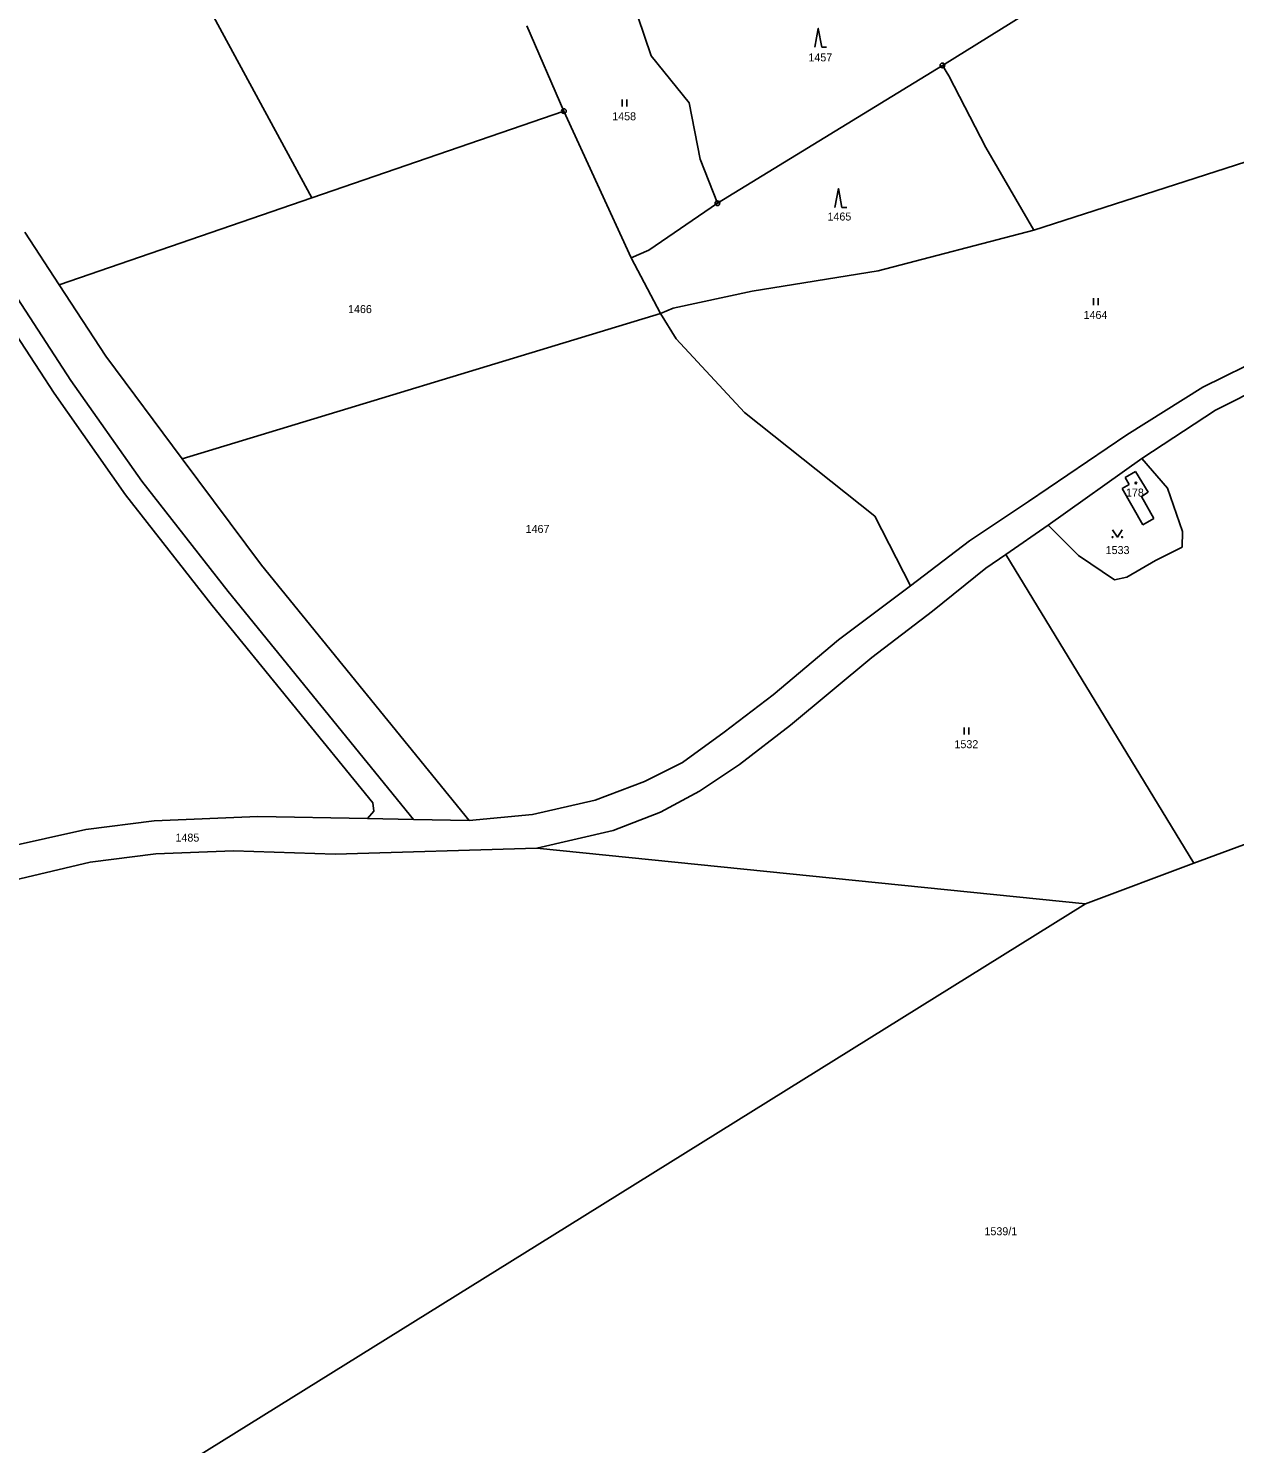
# Model space of a CAD drawing. Extents: x -601131 to -597152, y -1058536 to -1055911.
# Drawn here: x -600092 to -599835.8, y -1057934.2 to -1057633.6 of the extents above; entities that cross this region are included whole.
import ezdxf
from ezdxf.enums import TextEntityAlignment as Align

# ---------------------------------------------------------------- set-up
doc = ezdxf.new("R2010")
doc.units = 0
doc.header["$LTSCALE"] = 0.68
for name, color, linetype, lineweight in [('1', 7, 'Continuous', 25), ('3', 7, 'Continuous', 25), ('5', 7, 'Continuous', 25), ('8', 7, 'Continuous', 25)]:
    doc.layers.add(name, color=color, linetype=linetype, lineweight=lineweight)
doc.layers.add('2', color=7, linetype='Continuous')

msp = doc.modelspace()

# ---------------------------------------------------------------- linework, layer by layer
at = {"layer": '1'}
for p, q in [((-600031.79, -1057669.6), (-600081.73, -1057577.23)), ((-599959.7, -1057639.42), (-599962.58, -1057631.06)), ((-599880.67, -1057630.78), (-599897.86, -1057641.47)), ((-599978.26, -1057651.17), (-599986.09, -1057633.05)), ((-599951.67, -1057649.45), (-599959.7, -1057639.42)), ((-599897.86, -1057641.47), (-599945.66, -1057670.73)), ((-599896.49, -1057643.71), (-599897.86, -1057641.47)), ((-599888.68, -1057658.87), (-599896.49, -1057643.71)), ((-599782.01, -1057645.31), (-599878.46, -1057676.47)), ((-599949.29, -1057661.41), (-599951.67, -1057649.45)), ((-599978.26, -1057651.17), (-600031.79, -1057669.6)), ((-599963.98, -1057682.33), (-599978.26, -1057651.17)), ((-599878.46, -1057676.47), (-599888.68, -1057658.87)), ((-599945.66, -1057670.73), (-599949.29, -1057661.41)), ((-600085.43, -1057688.07), (-600031.79, -1057669.6)), ((-599945.66, -1057670.73), (-599960.2, -1057680.68)), ((-600092.74, -1057676.87), (-600085.43, -1057688.07)), ((-599911.5, -1057685.13), (-599878.46, -1057676.47)), ((-600100.49, -1057681.44), (-600082.92, -1057708.39)), ((-599960.2, -1057680.68), (-599963.98, -1057682.33)), ((-599963.98, -1057682.33), (-599957.74, -1057694.14)), ((-600104.38, -1057683.71), (-600086.5, -1057711.11)), ((-599938.24, -1057689.4), (-599911.5, -1057685.13)), ((-600075.53, -1057703.25), (-600085.43, -1057688.07)), ((-599955.07, -1057693), (-599938.24, -1057689.4)), ((-600059.3, -1057725.04), (-599957.74, -1057694.14)), ((-599957.74, -1057694.14), (-599955.07, -1057693)), ((-599954.38, -1057699.57), (-599957.74, -1057694.14)), ((-599939.91, -1057715.17), (-599954.38, -1057699.57)), ((-599820.76, -1057698.99), (-599842.59, -1057709.8)), ((-600059.3, -1057725.04), (-600075.53, -1057703.25)), ((-599839.9, -1057714.66), (-599819.15, -1057704.19)), ((-600082.92, -1057708.39), (-600067.9, -1057729.77)), ((-599842.59, -1057709.8), (-599858.7, -1057719.94)), ((-600086.5, -1057711.11), (-600071.35, -1057732.65)), ((-599912.24, -1057737.19), (-599939.91, -1057715.17)), ((-599855.56, -1057724.96), (-599839.9, -1057714.66)), ((-599858.7, -1057719.94), (-599879.62, -1057734.06)), ((-600042.5, -1057747.6), (-600059.3, -1057725.04)), ((-599875.39, -1057739.14), (-599855.56, -1057724.96)), ((-599850.1, -1057731.26), (-599855.56, -1057724.96)), ((-599859.04, -1057728.99), (-599856.91, -1057727.72)), ((-599856.91, -1057727.72), (-599854.22, -1057732.12)), ((-600067.9, -1057729.77), (-600049.57, -1057753.17)), ((-599859.68, -1057731.31), (-599858.2, -1057730.47)), ((-599858.2, -1057730.47), (-599859.04, -1057728.99)), ((-599846.88, -1057740.43), (-599850.1, -1057731.26)), ((-600071.35, -1057732.65), (-600052.94, -1057756.15)), ((-599879.62, -1057734.06), (-599892.09, -1057742.45)), ((-599855.29, -1057739.02), (-599859.68, -1057731.31)), ((-599854.22, -1057732.12), (-599855.63, -1057733.04)), ((-599855.63, -1057733.04), (-599852.97, -1057737.71)), ((-599904.67, -1057751.96), (-599912.24, -1057737.19)), ((-599884.41, -1057745.32), (-599875.39, -1057739.14)), ((-599875.39, -1057739.14), (-599868.99, -1057745.58)), ((-599852.97, -1057737.71), (-599855.29, -1057739.02)), ((-599892.09, -1057742.45), (-599904.67, -1057751.96)), ((-599846.99, -1057743.76), (-599846.88, -1057740.43)), ((-599888.63, -1057748.21), (-599884.41, -1057745.32)), ((-599844.46, -1057810.92), (-599884.41, -1057745.32)), ((-599868.99, -1057745.58), (-599861.36, -1057750.72)), ((-599852.64, -1057746.62), (-599846.99, -1057743.76)), ((-599998.39, -1057801.82), (-600042.5, -1057747.6)), ((-599899.96, -1057757.4), (-599888.63, -1057748.21)), ((-599858.73, -1057750.14), (-599852.64, -1057746.62)), ((-599904.67, -1057751.96), (-599919.94, -1057763.49)), ((-599861.36, -1057750.72), (-599858.73, -1057750.14)), ((-600049.57, -1057753.17), (-600010.2, -1057801.61)), ((-600052.94, -1057756.15), (-600018.85, -1057798.07)), ((-599912.87, -1057767.24), (-599899.96, -1057757.4)), ((-599919.94, -1057763.49), (-599933.84, -1057775.17)), ((-599930.12, -1057781.57), (-599912.87, -1057767.24)), ((-599933.84, -1057775.17), (-599944.19, -1057783.06)), ((-599940.94, -1057789.94), (-599930.12, -1057781.57)), ((-599944.19, -1057783.06), (-599953.07, -1057789.52)), ((-599953.07, -1057789.52), (-599961.12, -1057793.57)), ((-599949.45, -1057795.62), (-599940.94, -1057789.94)), ((-599961.12, -1057793.57), (-599971.59, -1057797.51)), ((-599957.76, -1057800.08), (-599949.45, -1057795.62)), ((-600018.58, -1057799.86), (-600019.99, -1057801.43)), ((-600018.85, -1057798.07), (-600018.58, -1057799.86)), ((-599971.59, -1057797.51), (-599984.92, -1057800.58)), ((-599967.79, -1057803.97), (-599957.76, -1057800.08)), ((-600065.27, -1057801.92), (-600079.8, -1057803.77)), ((-600043.22, -1057801), (-600065.27, -1057801.92)), ((-600019.99, -1057801.43), (-600043.22, -1057801)), ((-600010.2, -1057801.61), (-600019.99, -1057801.43)), ((-600010.2, -1057801.61), (-599998.39, -1057801.82)), ((-599984.92, -1057800.58), (-599998.39, -1057801.82)), ((-600079.8, -1057803.77), (-600096.87, -1057807.55)), ((-599983.99, -1057807.73), (-599967.79, -1057803.97)), ((-600078.87, -1057810.71), (-600064.88, -1057808.91)), ((-600064.88, -1057808.91), (-600048.42, -1057808.26)), ((-600048.42, -1057808.26), (-600026.8, -1057808.95)), ((-600026.8, -1057808.95), (-599983.99, -1057807.73)), ((-599867.48, -1057819.51), (-599983.99, -1057807.73)), ((-600094.97, -1057814.53), (-600078.87, -1057810.71)), ((-599844.46, -1057810.92), (-599867.48, -1057819.51)), ((-599980.76, -1057890.01), (-599867.48, -1057819.51)), ((-600094.05, -1057960.5), (-599980.76, -1057890.01))]:
    msp.add_line(p, q, dxfattribs=at)
msp.add_lwpolyline([(-599844.46, -1057810.92), (-599812.82, -1057799.18), (-599800.5, -1057863.35)], dxfattribs=at)
at = {"layer": '3'}
for p, q in [((-599923.48, -1057637.63), (-599922.484, -1057637.63)), ((-599965.871, -1057650.23), (-599965.871, -1057648.73)), ((-599964.87, -1057650.23), (-599964.87, -1057648.73)), ((-599919.2, -1057671.64), (-599918.204, -1057671.64)), ((-599865.771, -1057692.4), (-599865.771, -1057690.9)), ((-599864.77, -1057692.4), (-599864.77, -1057690.9)), ((-599893.251, -1057783.58), (-599893.251, -1057782.08)), ((-599892.25, -1057783.58), (-599892.25, -1057782.08))]:
    msp.add_line(p, q, dxfattribs=at)
for points in [[(-599923.48, -1057637.63), (-599924.23, -1057633.63), (-599924.98, -1057637.63)], [(-599919.2, -1057671.64), (-599919.95, -1057667.64), (-599920.7, -1057671.64)], [(-599861.73, -1057740.129), (-599860.73, -1057741.63), (-599859.73, -1057740.129)]]:
    msp.add_lwpolyline(points, dxfattribs=at)
for centre in [(-599861.73, -1057741.6295), (-599859.73, -1057741.6295)]:
    msp.add_circle(centre, 0.1, dxfattribs=at)
at = {"layer": '5'}
msp.add_circle((-599856.7968, -1057730.1692), 0.175, dxfattribs=at)
at = {"layer": '8'}
for centre, radius in [((-599897.86, -1057641.4699), 0.5), ((-599897.86, -1057641.4699), 0.0303), ((-599978.26, -1057651.1699), 0.5), ((-599978.26, -1057651.1699), 0.0303), ((-599945.66, -1057670.7299), 0.5), ((-599945.66, -1057670.7299), 0.0303)]:
    msp.add_circle(centre, radius, dxfattribs=at)

# ---------------------------------------------------------------- texts
at = {"layer": '2'}
for s, p in [('1457', (-599923.8, -1057640.612)), ('1458', (-599965.46, -1057653.122)), ('1465', (-599919.75, -1057674.412)), ('1466', (-600021.56, -1057694.072)), ('1464', (-599865.37, -1057695.312)), ('178', (-599856.999, -1057733.032)), ('1467', (-599983.85, -1057740.762)), ('1533', (-599860.68, -1057745.252)), ('1532', (-599892.79, -1057786.472)), ('1485', (-600058.2, -1057806.312)), ('1539/1', (-599885.47, -1057889.915))]:
    msp.add_text(s, height=1.7, dxfattribs=at).set_placement(p, align=Align.CENTER)

doc.saveas('drawing.dxf')
